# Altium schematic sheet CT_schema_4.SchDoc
size 573 x 363 mm
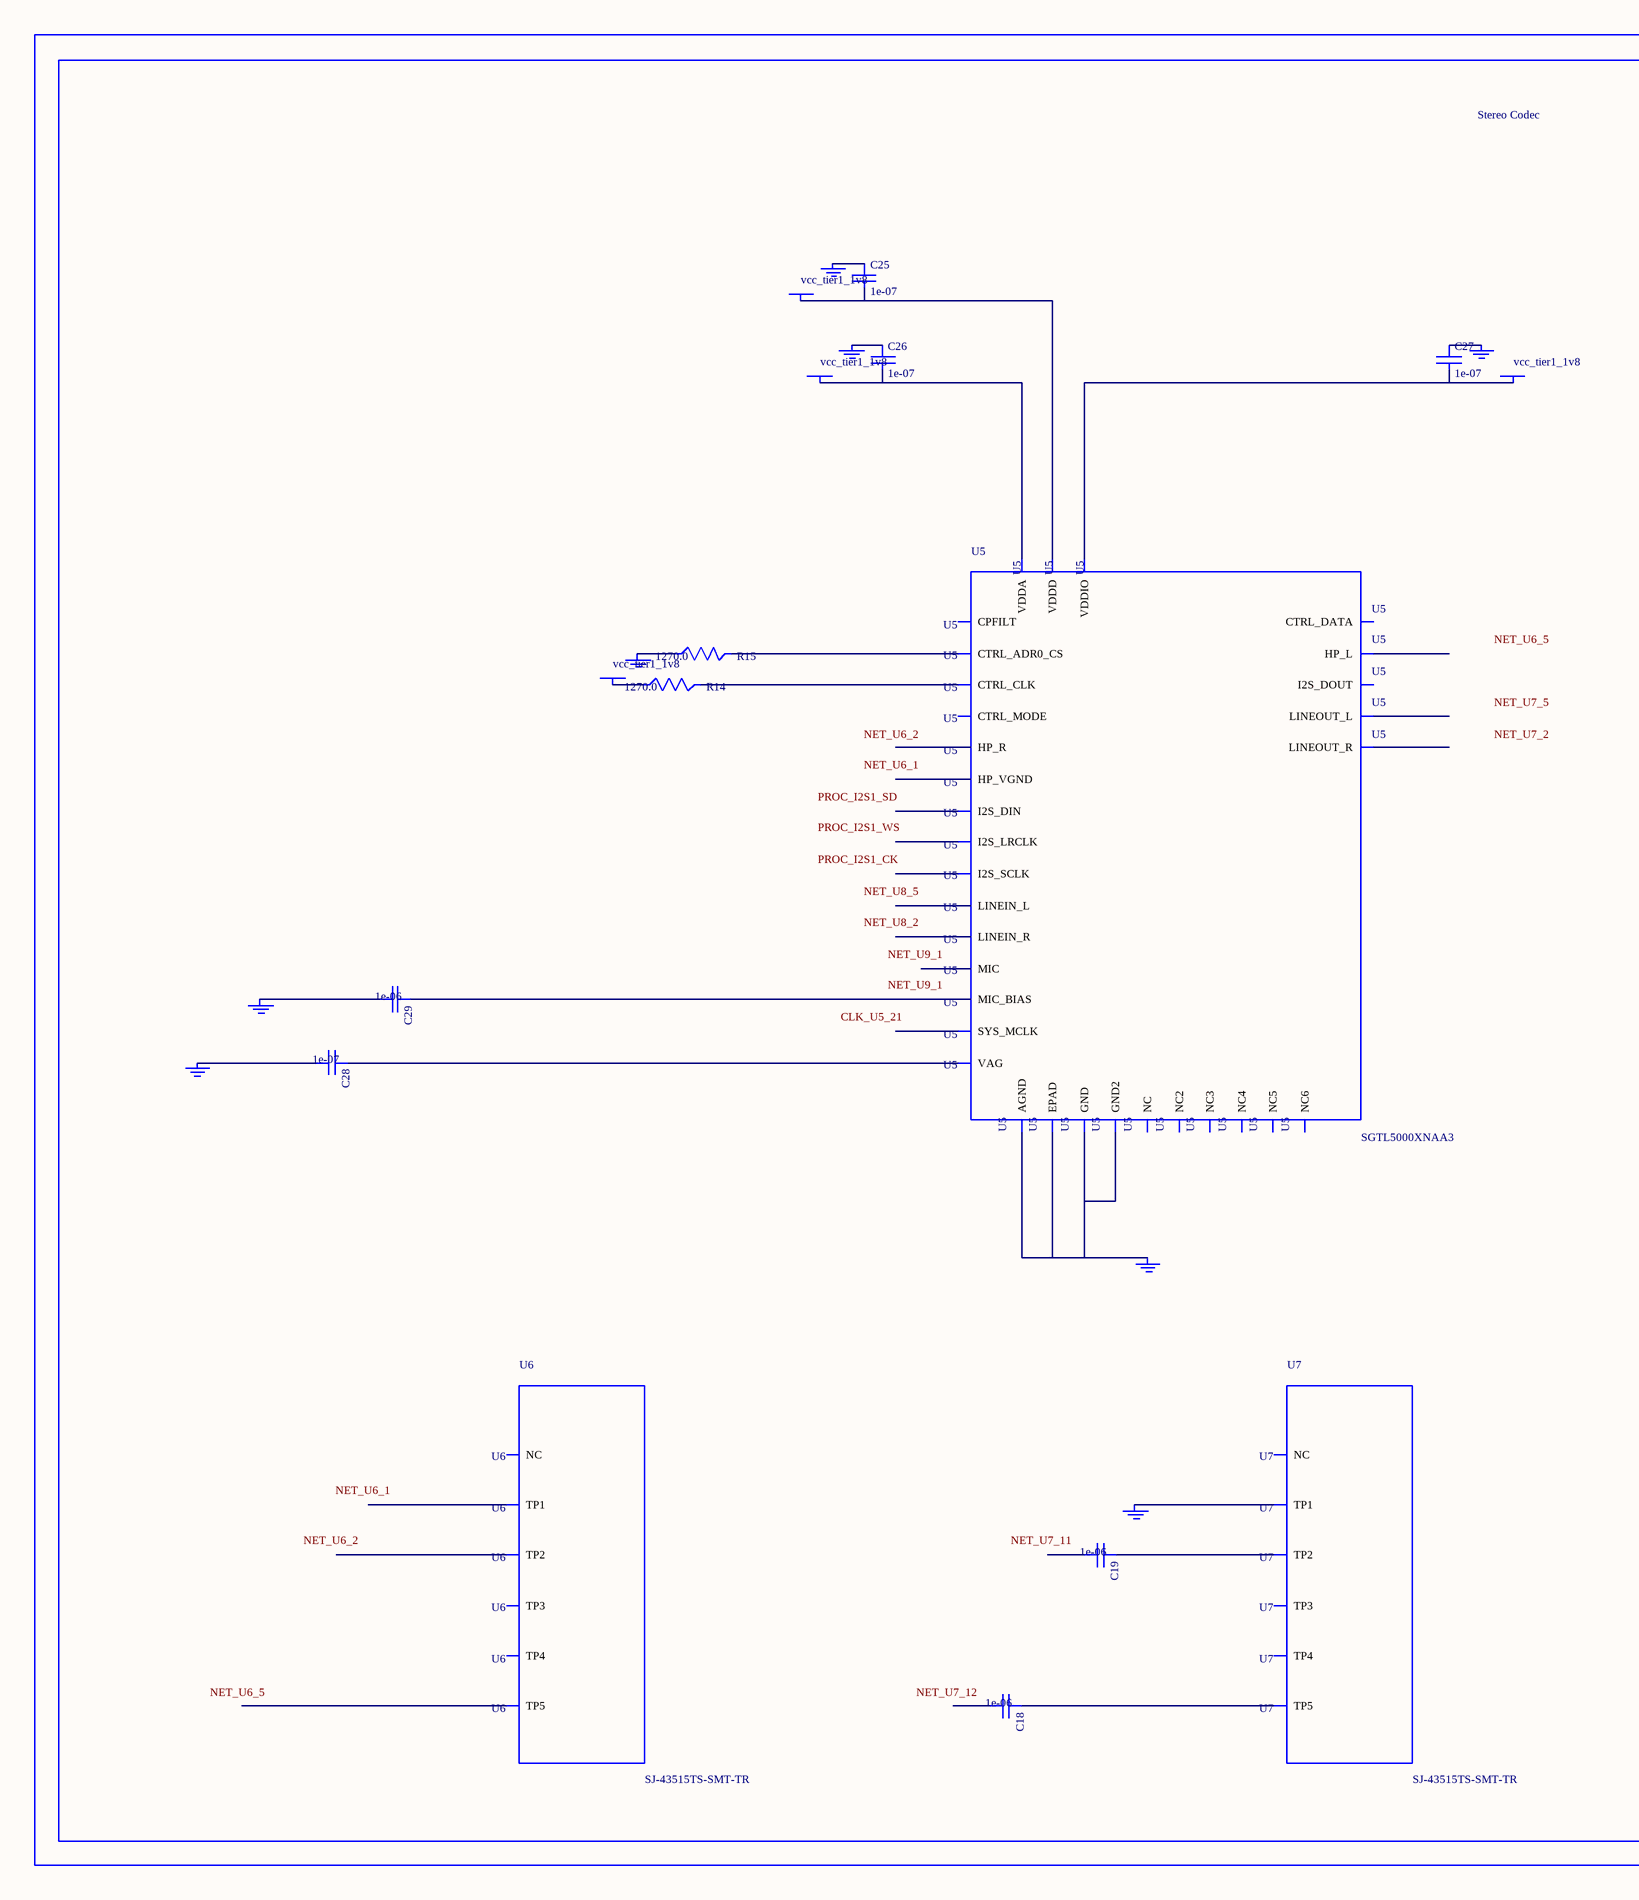
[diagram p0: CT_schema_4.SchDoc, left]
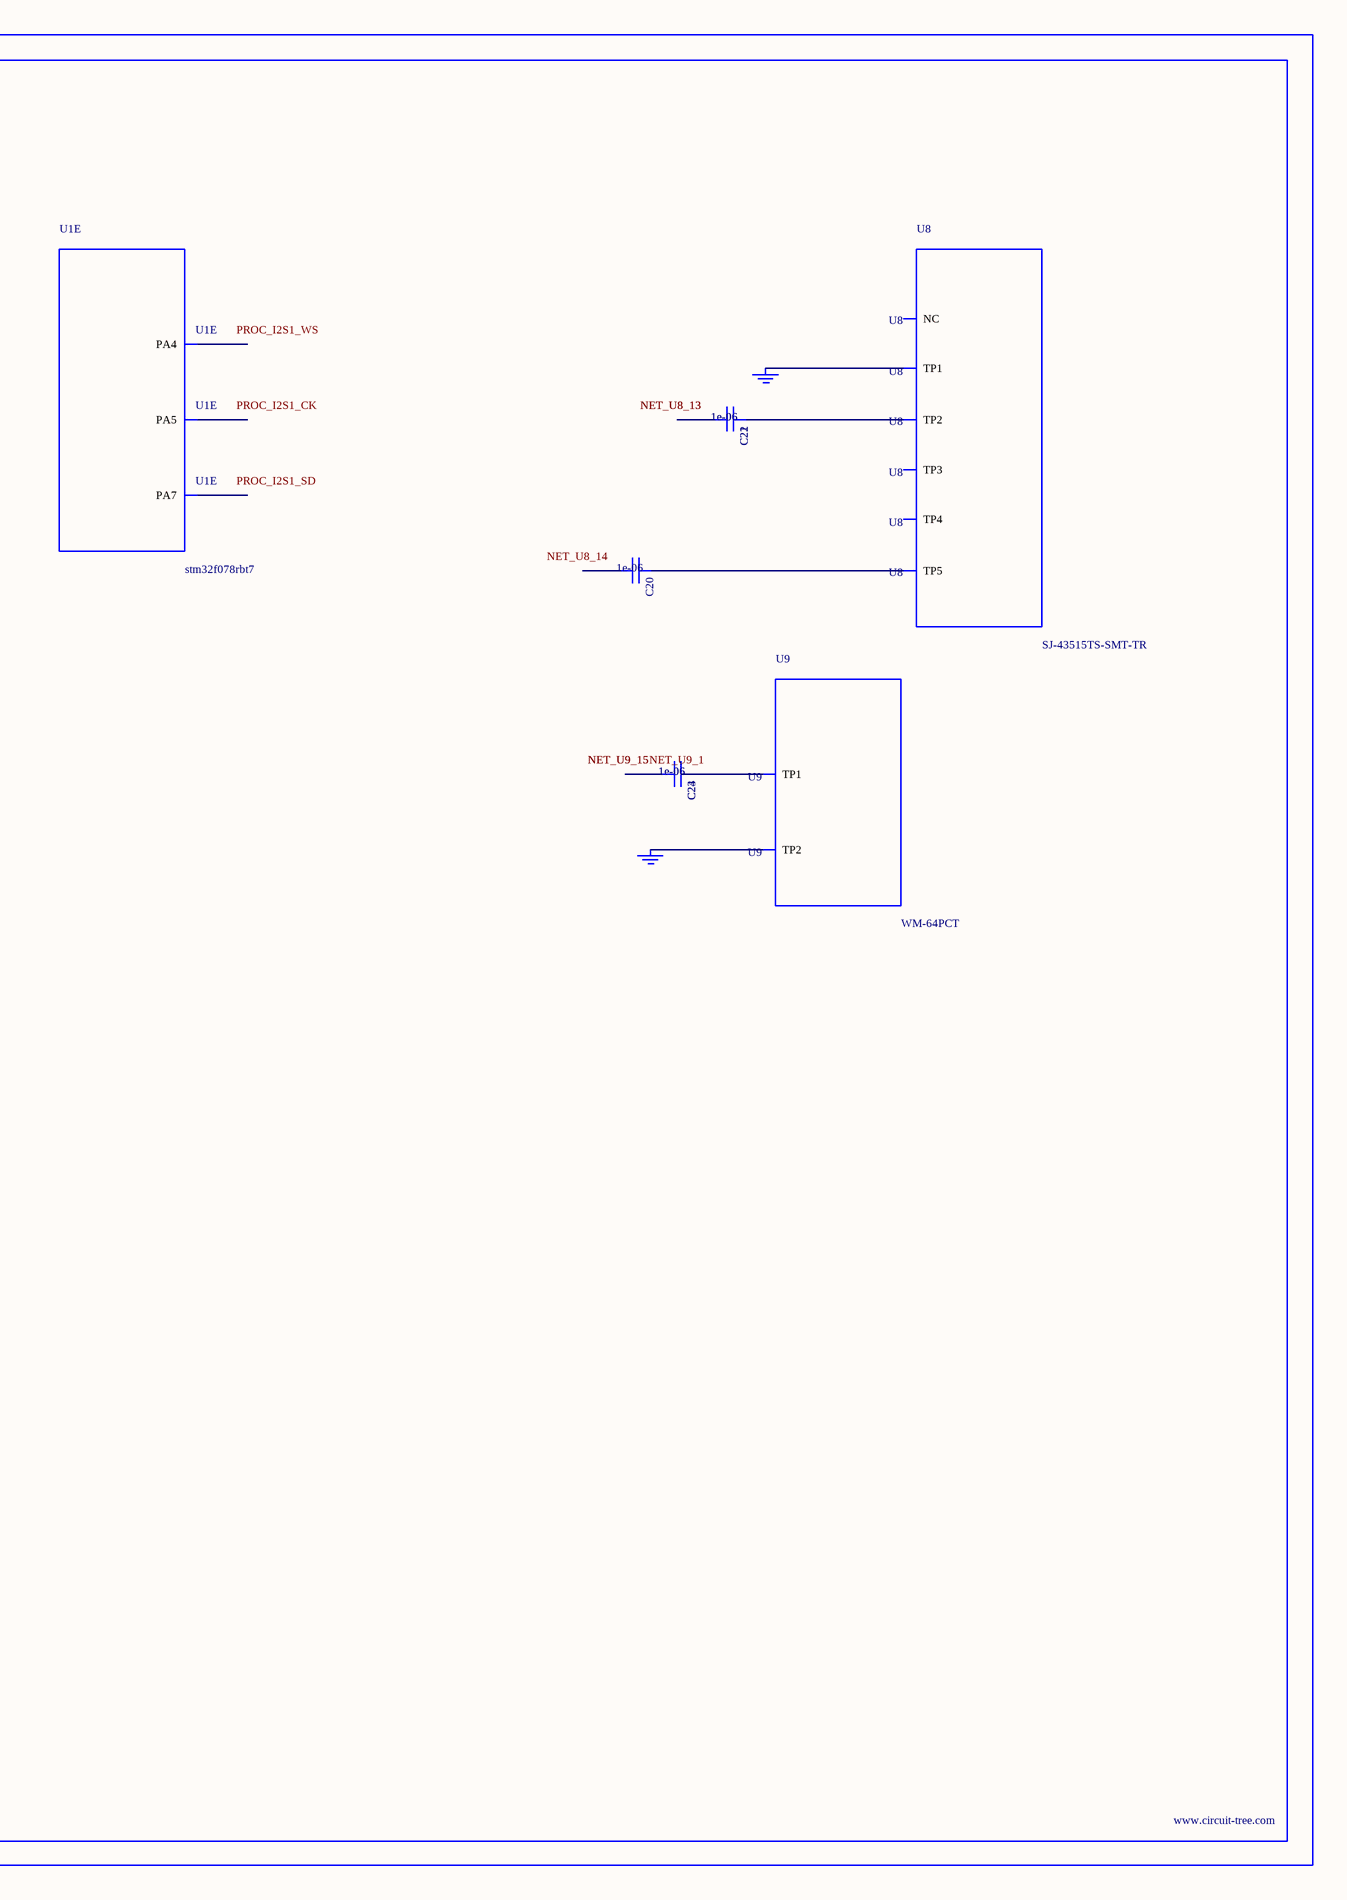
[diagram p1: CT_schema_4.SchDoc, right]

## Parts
BORDER3  (no value)
C18  1e-06  [C0603]
C19  1e-06  [C0603]
C20  1e-06  [C0603]
C21  1e-06  [C0603]
C22  1e-06  [C0603]
C23  1e-06  [C0603]
C24  1e-06  [C0603]
C25  1e-07  [C0402]
C26  1e-07  [C0402]
C27  1e-07  [C0402]
C28  1e-07  [C0402]
C29  1e-06  [C0603]
GND_INSTANCE_3_0  (no value)
GND_INSTANCE_3_1  (no value)
GND_INSTANCE_3_2  (no value)
GND_INSTANCE_3_3  (no value)
GND_INSTANCE_3_4  (no value)
GND_INSTANCE_3_5  (no value)
GND_INSTANCE_3_6  (no value)
GND_INSTANCE_3_7  (no value)
GND_INSTANCE_3_8  (no value)
GND_INSTANCE_3_9  (no value)
GND_INSTANCE_3_10  (no value)
POWER_INSTANCE_3_0  vcc_tier1_1v8
POWER_INSTANCE_3_1  vcc_tier1_1v8
POWER_INSTANCE_3_2  vcc_tier1_1v8
POWER_INSTANCE_3_3  vcc_tier1_1v8
R14  1270.0  [R0603]
R15  1270.0  [R0603]
U1  stm32f078rbt7  [LQFP64]  (part E of 7)
U5  SGTL5000XNAA3  [QFN-32]
U6  SJ-43515TS-SMT-TR  [SJ-43515TS-SMT-TR]
U7  SJ-43515TS-SMT-TR  [SJ-43515TS-SMT-TR]
U8  SJ-43515TS-SMT-TR  [SJ-43515TS-SMT-TR]
U9  WM-64PCT  [WM-64PC]

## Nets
NetC18_1: C18.1 U7.5(TP5)
NetC19_1: C19.1 U7.2(TP2)
NetC20_1: C20.1 U8.5(TP5)
NetC21_1: C21.1 C22.1 U8.2(TP2)
NetC21_2: C21.2 C22.2
NetC23_1: C23.1 C24.1 U9.1(TP1)
NetC23_2: C23.2 C24.2
NetC25_1: C25.1 GND_INSTANCE_3_5.0(GND)
NetC25_2: C25.2 POWER_INSTANCE_3_3.0(PWR) U5.30(VDDD)
NetC26_1: C26.1 GND_INSTANCE_3_1.0(GND)
NetC26_2: C26.2 POWER_INSTANCE_3_0.0(PWR) U5.5(VDDA)
NetC27_1: C27.1 GND_INSTANCE_3_4.0(GND)
NetC27_2: C27.2 POWER_INSTANCE_3_1.0(PWR) U5.20(VDDIO)
NetC28_1: C28.1 U5.10(VAG)
NetC28_2: C28.2 GND_INSTANCE_3_2.0(GND)
NetC29_1: C29.1 U5.16(MIC_BIAS)
NetC29_2: C29.2 GND_INSTANCE_3_3.0(GND)
NetGND_INSTANCE_3_0_0: GND_INSTANCE_3_0.0(GND) U5.1(GND) U5.3(GND2) U5.7(AGND) U5.EXP(EPAD)
NetGND_INSTANCE_3_6_0: GND_INSTANCE_3_6.0(GND) R15.1
NetGND_INSTANCE_3_7_0: GND_INSTANCE_3_7.0(GND) U7.1(TP1)
NetGND_INSTANCE_3_8_0: GND_INSTANCE_3_8.0(GND) GND_INSTANCE_3_9.0(GND) U8.1(TP1)
NetGND_INSTANCE_3_10_0: GND_INSTANCE_3_10.0(GND) U9.2(TP2)
NetPOWER_INSTANCE_3_2_0: POWER_INSTANCE_3_2.0(PWR) R14.1
NetR14_2: R14.2 U5.29(CTRL_CLK)
NetR15_2: R15.2 U5.31(CTRL_ADR0_CS)

Not connected (* = marked no-connect by the designer): C18 2; C19 2; C20 2; U1 20(PA4) 21(PA5) 23(PA7); U5 2(HP_R) 4(HP_VGND) 6(HP_L) 8(NC) 9(NC2) 11(LINEOUT_R) 12(LINEOUT_L) 13(LINEIN_R) 14(LINEIN_L) 15(MIC) 17(NC3) 18(CPFILT) 19(NC4) 21(SYS_MCLK) 22(NC5) 23(I2S_LRCLK) 24(I2S_SCLK) 25(I2S_DOUT) 26(I2S_DIN) 27(CTRL_DATA) 28(NC6) 32(CTRL_MODE); U6 1(TP1) 2(TP2) 3(TP3) 4(TP4) 5(TP5) 6(NC); U7 3(TP3) 4(TP4) 6(NC); U8 3(TP3) 4(TP4) 6(NC)

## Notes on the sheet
- Labels drawn without touching a wire or pin: CLK_U5_21, NET_U6_1, NET_U6_2, NET_U6_5, NET_U7_2, NET_U7_5, NET_U7_11, NET_U7_12, NET_U8_2, NET_U8_5, NET_U8_14, NET_U9_1, PROC_I2S1_CK, PROC_I2S1_SD, PROC_I2S1_WS

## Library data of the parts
BORDER3 = BORDER_PAGE3
C18-C24 C29 = C0603C105K3RACTU
C25-C28 = C0402C104K3RACTU
GND_INSTANCE_3_0-GND_INSTANCE_3_10 = GND
POWER_INSTANCE_3_0-POWER_INSTANCE_3_3 = PWR
R14 R15 = RC0603FR-071K27L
